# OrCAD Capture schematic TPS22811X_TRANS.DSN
size E; title: TPS22811x 2.7 V–16 V, 10-A, 6-mO Load Switch with Adjustable; rev: 1.0; note: Datasheet: SLVSGU5    EVM: SLVUCE4; note: Current Monitor and Transient Overcurrent Blanking
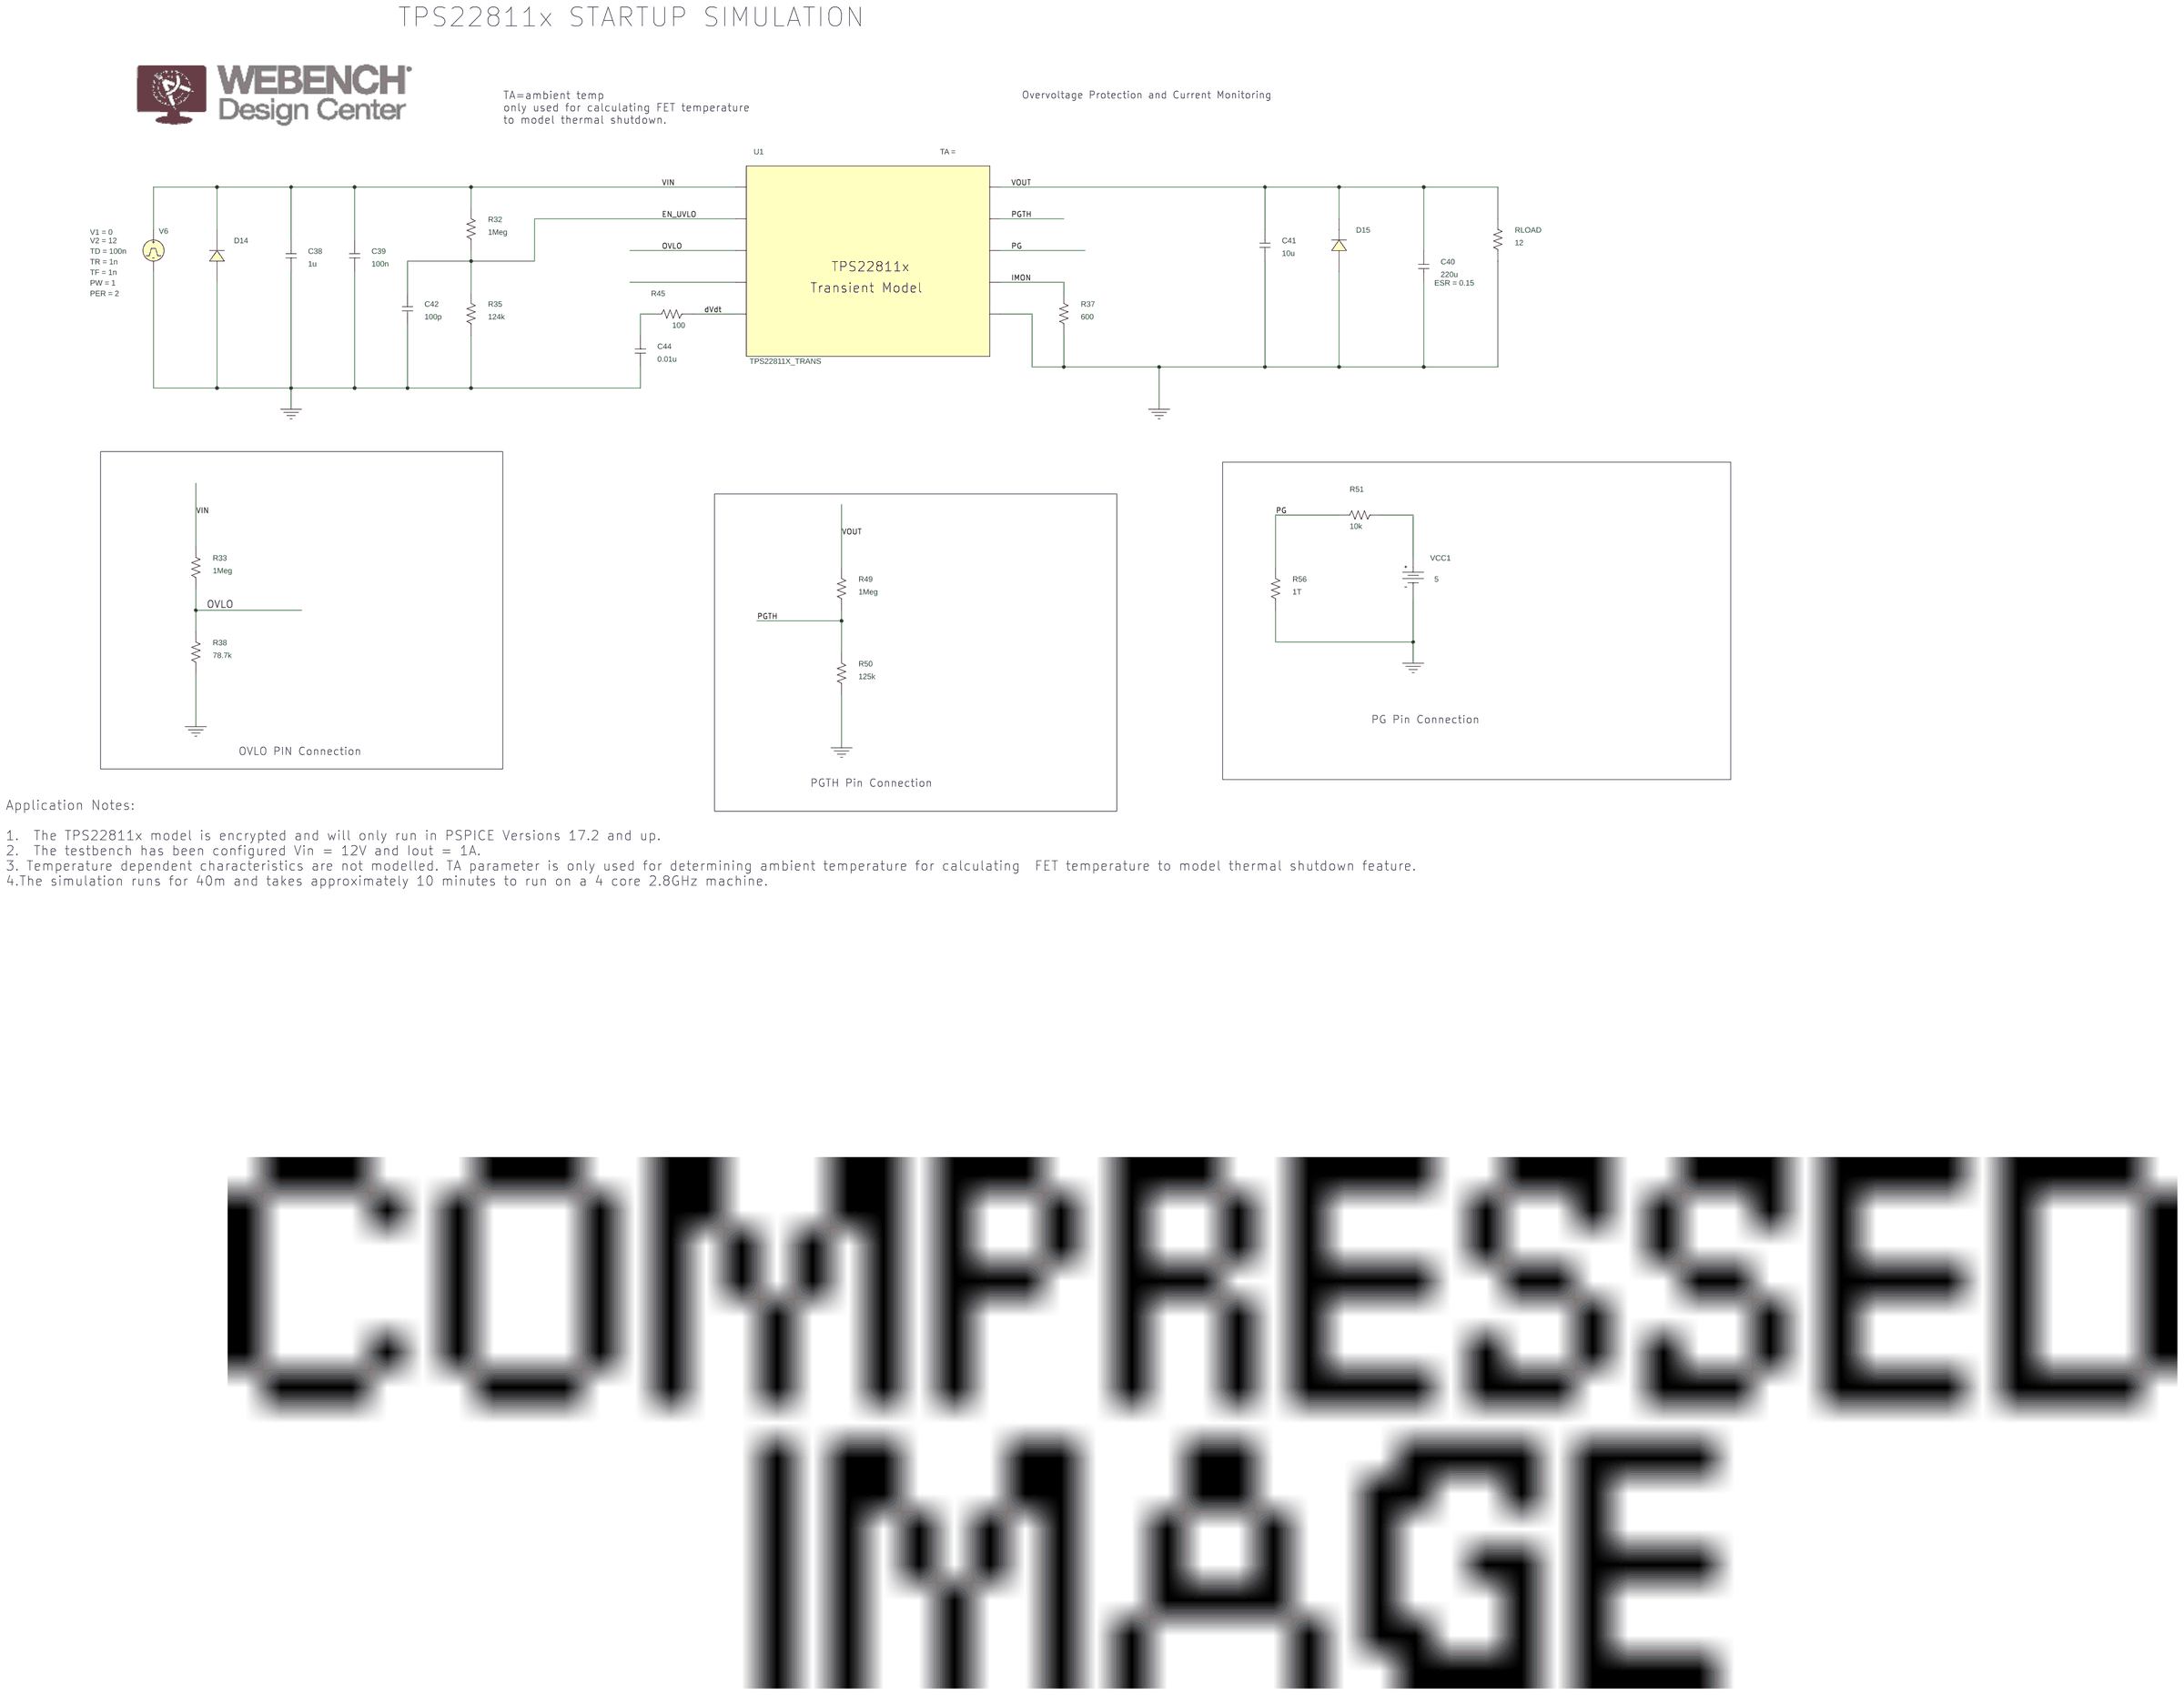
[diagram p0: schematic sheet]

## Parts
C38  1u  [RAD/CK05]
C39  100n  [RAD/CK05]
C40  220u  [RAD/CK05]
C41  10u  [RAD/CK05]
C42  100p  [RAD/CK05]
C44  0.01u  [RAD/CK05]
D14  SMBJ18A
D15  B330A
R32  1Meg  [AX/RC05]
R33  1Meg  [AX/RC05]
R35  124k  [AX/RC05]
R37  600  [AX/RC05]
R38  78.7k  [AX/RC05]
R45  100  [AX/RC05]
R49  1Meg  [AX/RC05]
R50  125k  [AX/RC05]
R51  10k  [AX/RC05]
R56  1T  [AX/RC05]
RLOAD  12  [AX/RC05]
U1  TPS22811X_TRANS
V6  VPULSE
VCC1  VDC

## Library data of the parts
C38 C39 C41 C42 C44 = C
C40 = C: AppProp: InductiveSlave:;SRF:;PrevCap:220u;PrevESL:; ESR: 0.15
D14 = D_D1: PSpiceTemplate: X^@REFDES  %C %A @MODEL
D15 = D_D1: PSpiceTemplate: D^@REFDES  %A %C @MODEL ?AREA/@AREA/
R32 R33 R35 R37 R38 R45 R49-R51 R56 RLOAD = R
U1 = TPS22811X_TRANS
V6 = VPULSE: PER: 2; PW: 1; TD: 100n; TF: 1n; TR: 1n; V1: 0; V2: 12
VCC1 = VDC: DC: 5

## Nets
VIN: C38.2 C39.2 D14.1(C) R32.2 R33.2 U1.IN V6.1(+)
0: C38.1 C39.1 C40.1 C41.1 C42.1 C44.1 D14.2(A) D15.2(A) R35.1 R37.1 R38.1 R50.1 R56.1 RLOAD.1 U1.GND V6.2(-) VCC1.1(-)
dVdt: R45.1 U1.DVDT
EN_UVLO: C42.2 R32.1 R35.2 U1.EN_UVLO
IMON: R37.2 U1.IMON
OVLO: R33.1 R38.2 U1.OVLO
PG: R51.2 R56.2 U1.PG
PGTH: R49.1 R50.2 U1.PGTH
VOUT: C40.2 C41.2 D15.1(C) R49.2 RLOAD.2 U1.OUT
N16780012: C44.2 R45.2
N16780128: R51.1 VCC1.0(+)

Not connected (* = marked no-connect by the designer): U1 NC

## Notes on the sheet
- TPS22811x STARTUP SIMULATION
- TA=ambient temp
  only used for calculating FET temperature
  to model thermal shutdown.
- Overvoltage Protection and Current Monitoring
- PG Pin Connection
- OVLO PIN Connection
- PGTH Pin Connection
- Application Notes:
  1.  The TPS22811x model is encrypted and will only run in PSPICE Versions 17.2 and up.
  2.  The testbench has been configured Vin = 12V and Iout = 1A.
  3. Temperature dependent characteristics are not modelled. TA parameter is only used for determining ambient temperature for calculating  FET temperature to model thermal shutdown feature.
  4.The simulation runs for 40m and takes approximately 10 minutes to run on a 4 core 2.8GHz machine.
